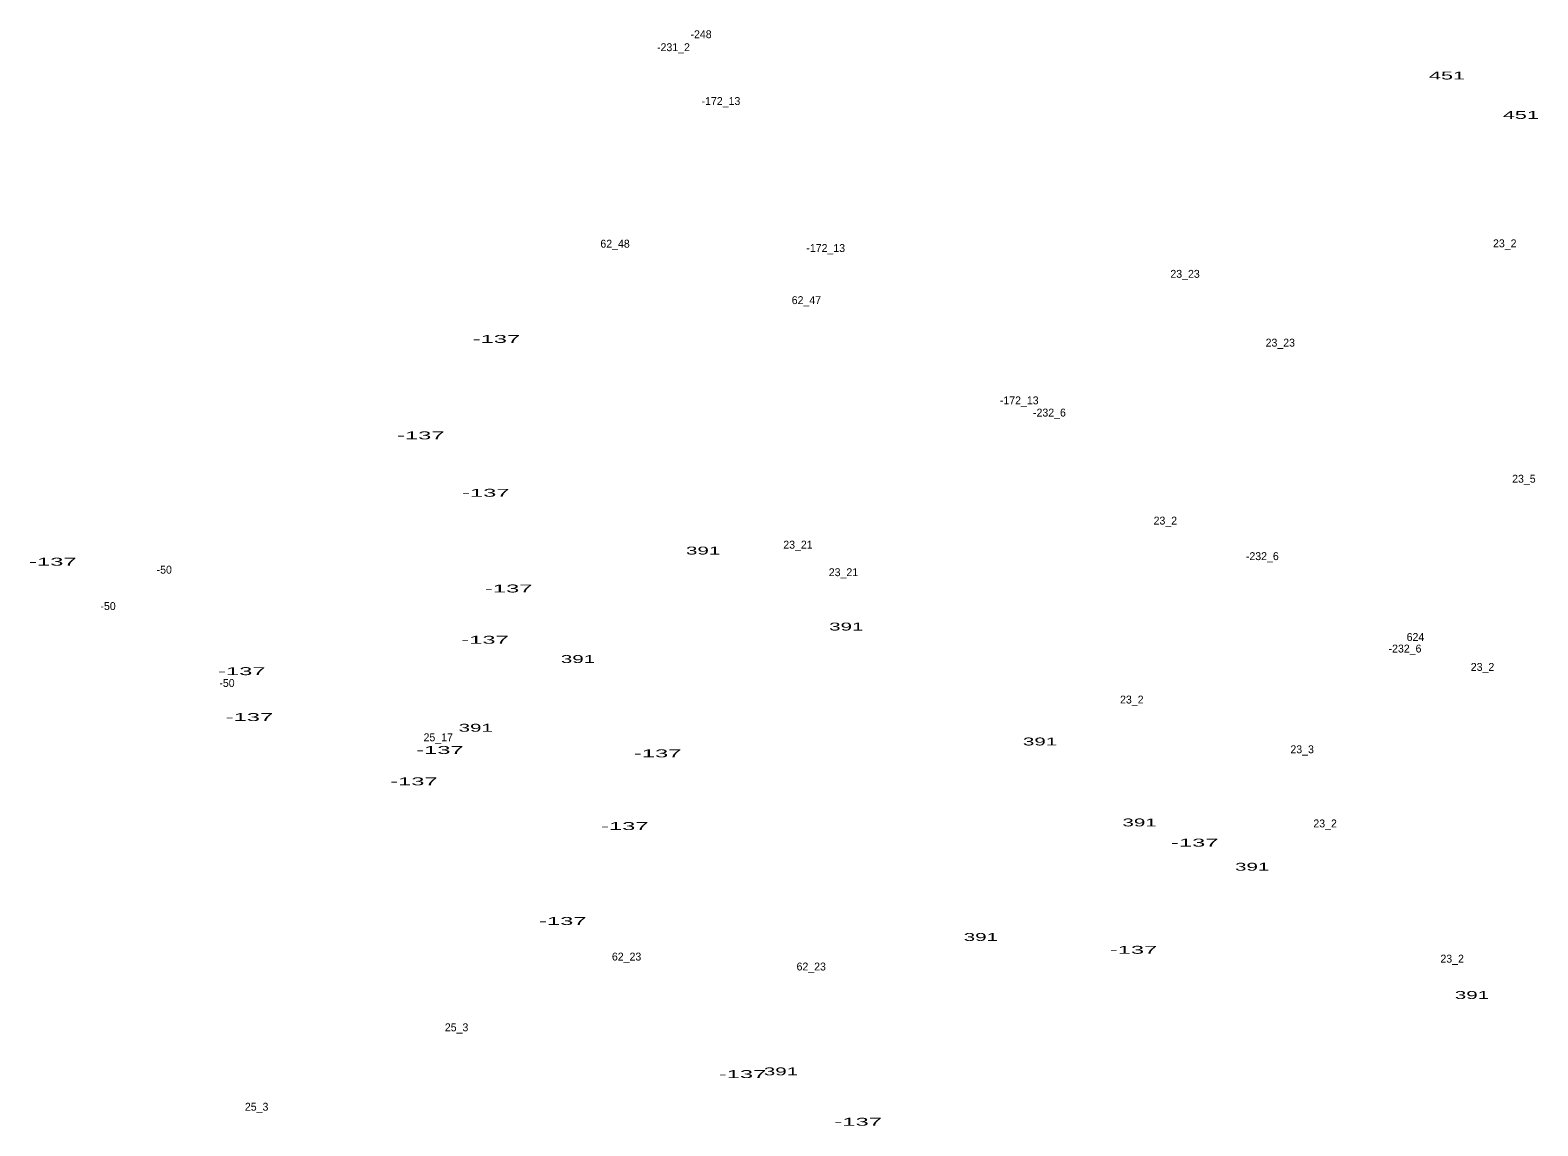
# Model space of a CAD drawing. Extents: x -661742 to -657295, y -1002932 to -996888.
# Drawn here: x -659245 to -658481, y -1000397 to -999841 of the extents above; entities that cross this region are included whole.
import ezdxf
from ezdxf.enums import TextEntityAlignment as Align

# ---------------------------------------------------------------- set-up
doc = ezdxf.new("R2010")
doc.units = 0
doc.header["$LTSCALE"] = 1.6
doc.layers.add('24', color=7, linetype='Continuous')

msp = doc.modelspace()

# ---------------------------------------------------------------- texts
at = {"layer": '24'}
for s, p in [('-248', (-658905.099, -999845.51)), ('-231_2', (-658919.096, -999852.08)), ('-172_13', (-658895.035, -999879.38)), ('62_48', (-658948.704, -999951.65)), ('-172_13', (-658841.915, -999953.85)), ('23_2', (-658497.685, -999951.47)), ('23_23', (-658659.745, -999966.93)), ('62_47', (-658851.7, -999980.26)), ('23_23', (-658611.475, -1000001.8)), ('-172_13', (-658743.815, -1000031.04)), ('-232_6', (-658728.498, -1000037.23)), ('23_5', (-658487.975, -1000070.75)), ('23_2', (-658669.745, -1000091.96)), ('23_21', (-658855.979, -1000104.16)), ('-232_6', (-658620.578, -1000109.98)), ('-50', (-659177.229, -1000116.84)), ('23_21', (-658832.919, -1000118.11)), ('-50', (-659205.719, -1000135.27)), ('624', (-658542.967, -1000150.96)), ('-232_6', (-658548.248, -1000156.8)), ('23_2', (-658508.945, -1000166.1)), ('-50', (-659145.429, -1000174.25)), ('23_2', (-658686.745, -1000182.64)), ('25_17', (-659038.344, -1000201.79)), ('23_3', (-658600.395, -1000207.85)), ('23_2', (-658588.755, -1000245.41)), ('62_23', (-658942.86, -1000312.89)), ('23_2', (-658524.345, -1000313.94)), ('62_23', (-658849.25, -1000317.92)), ('25_3', (-659029.035, -1000348.73)), ('25_3', (-659130.405, -1000388.98))]:
    msp.add_text(s, height=4, dxfattribs=at).set_placement(p, align=Align.CENTER)
for s, width, p in [('451', 2.05, (-658526.943, -999866.44)), ('451', 2.05, (-658489.523, -999886.42)), ('-137', 2.25, (-659008.815, -999999.91)), ('-137', 2.25, (-659047.205, -1000048.78)), ('-137', 2.25, (-659014.245, -1000077.87)), ('391', 1.95, (-658904.053, -1000107.16)), ('-137', 2.25, (-659233.705, -1000112.78)), ('-137', 2.25, (-659002.615, -1000126.36)), ('391', 1.95, (-658831.493, -1000145.66)), ('-137', 2.25, (-659014.635, -1000152.35)), ('391', 1.95, (-658967.493, -1000162.11)), ('-137', 2.25, (-659137.935, -1000168.25)), ('-137', 2.25, (-659134.055, -1000191.52)), ('391', 1.95, (-659019.323, -1000196.94)), ('-137', 2.25, (-659037.505, -1000208.2)), ('391', 1.95, (-658733.243, -1000203.9)), ('-137', 2.25, (-658927.115, -1000209.91)), ('-137', 2.25, (-659050.685, -1000224.1)), ('-137', 2.25, (-658943.785, -1000246.75)), ('391', 1.95, (-658682.803, -1000244.92)), ('-137', 2.25, (-658654.845, -1000255.15)), ('391', 1.95, (-658625.713, -1000267.36)), ('-137', 2.25, (-658975.195, -1000294.85)), ('391', 1.95, (-658763.263, -1000302.96)), ('-137', 2.25, (-658685.865, -1000309.45)), ('391', 1.95, (-658514.313, -1000332.36)), ('-137', 2.25, (-658884.075, -1000372.43)), ('391', 1.95, (-658864.603, -1000371.06)), ('-137', 2.25, (-658825.455, -1000396.59))]:
    msp.add_text(s, height=4, dxfattribs=dict(at, width=width)).set_placement(p, align=Align.CENTER)

doc.saveas('drawing.dxf')
